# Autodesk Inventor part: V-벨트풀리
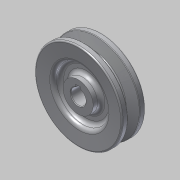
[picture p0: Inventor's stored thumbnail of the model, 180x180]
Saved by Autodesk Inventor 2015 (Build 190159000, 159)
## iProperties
Created: 2016-08
Part Number: V-벨트풀리
Material: 알루미늄 6061
Document SubType Name: Modeling
Designer: mduedu
Density: 2.71 g/cm^3
Appearance: 알루미늄 - 평지
Author: mduedu
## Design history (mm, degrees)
sketch "스케치1"
  geometry: L1 (0, 9.5)-(0, -9.5); L2 (0, 9.5)-(35, 9.5); L3 (35, 9.5)-(35, 4.825); L4 (35, 4.825)-(26, 2.074); L5 (26, 2.074)-(26, 0); L6 (0, 0)-(26, 0); L7 (0, -9.5)-(35, -9.5); L8 (35, -9.5)-(35, -4.825); L9 (35, -4.825)-(26, -2.074); L10 (26, -2.074)-(26, 0); L11 (32.3, 9.5)-(32.3, -9.5); 3 further points
  constraints: 22 end point, 6 point on line, 4 perpendicular, 3 symmetric about line, 1 coincident, 1 horizontal alignment, 1 midpoint, 1 parallel, 1 vertical
  dimensions: "d0" = 19 distance of L1.start L1.end; "d2" = 70 diameter of L8 L1; "d4" = 6.3 distance between parallel lines of L10 L11; "d5" = 2.7 distance between parallel lines of L11 L8; "d6" = 8 distance of point (32.3, -4) point (32.3, 4); "d7" = 34 deg angle of L9 L4
revolve "회전1" sketch "스케치1" stored, may be unused: angle "d8" = 90 deg
sketch "스케치2"
  geometry: L1 (-2, 0)-(2, 0); L2 (2, 0)-(2, 7.8); L3 (2, 7.8)-(-2, 7.8); L4 (-2, 7.8)-(-2, 0); C1 r 6 at (0, 0); 2 further points
  constraints: 8 end point, 2 coincident, 2 parallel, 1 centre point, 1 horizontal, 1 midpoint, 1 perpendicular
  dimensions: "d9" = 12 diameter of C1; "d11" = 4 distance of L2.end L3.end; "d12" = 7.8 distance of L1.end L2.end
extrude "돌출1" cut sketch "스케치2" stored distance "d13" = 10; taper "d14" = 0 deg
sketch "스케치3"
  geometry: L1 (35, 4.825)-(26, 2.074) reference; L2 (26, 2.074)-(26, -2.074) reference; L3 (0, 0)-(26, 0); L4 (35, 9.5)-(35, 4.825) reference; L5 (-35, 9.5)-(35, 9.5) reference; L6 (35, 9.5)-(21, 8.275); L7 (21, 8.275)-(21, 3); L8 (21, 3)-(12, 3); L9 (12, 3)-(12, 9.5); L10 (0, 9.5)-(0, -9.5); L11 (5.657, -9.5)-(-6, -9.5) reference; L12 (12, 9.5)-(35, 9.5)
  constraints: 14 end point, 3 midpoint, 2 perpendicular, 2 point on line, 1 collinear, 1 horizontal, 1 parallel
  dimensions: "d15" = 3 distance between parallel lines of L3 L8; "d17" = 42 diameter of L7 L10; "d18" = 24 diameter of L9 L10; "d31" = 5 deg angle of L6 L5
revolve "회전2" sketch "스케치3" stored, may be unused: angle "d19" = 90 deg
fillet "모깎기1" dims "d20" = 0.5, "d21" = 1, "d22" = 1
fillet "모깎기2" dims "d23" = 3
fillet "모깎기3" dims "d24" = 3
fillet "모깎기4" dims "d25" = 3
chamfer "모따기1" distance "d26" = 0.5; stored, may be unused: second distance "d27" = 2, angle "d28" = 45 deg
node "솔리드1"
mirror "대칭1"
